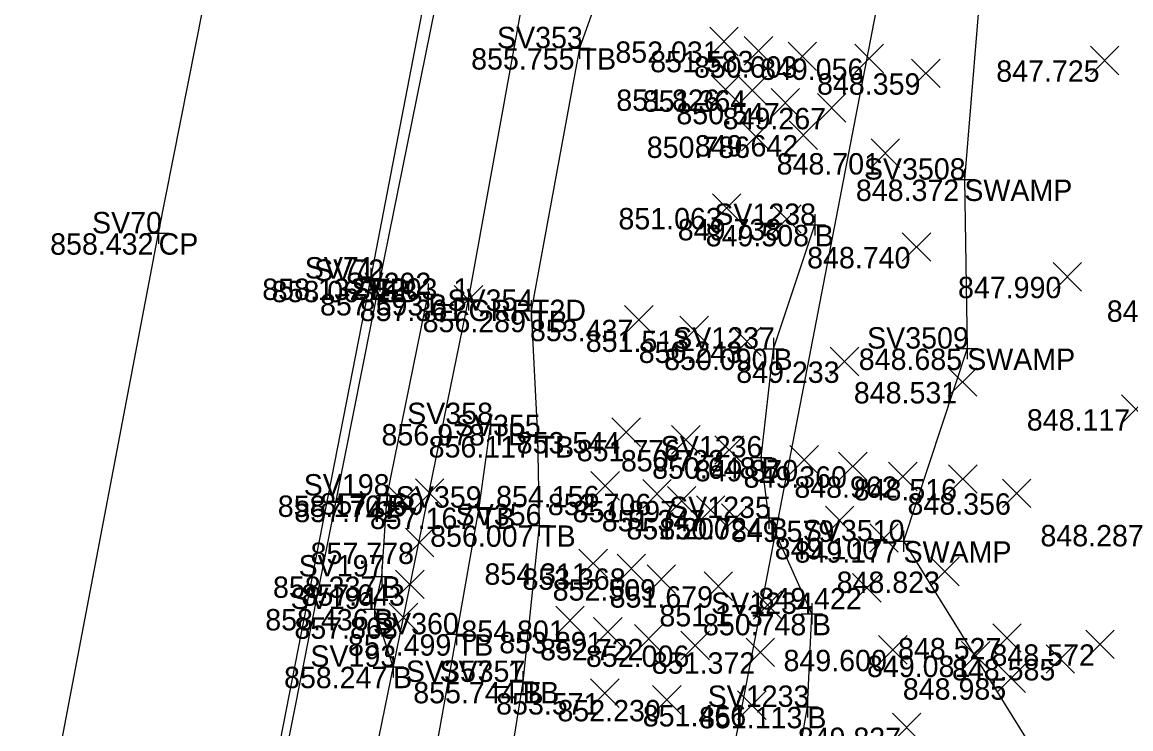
# Model space of a CAD drawing. Extents: x 2228183 to 2230895, y 679226 to 682223.
# Drawn here: x 2228291.3 to 2228343.2, y 680493.8 to 680526.8 of the extents above; entities that cross this region are included whole.
import ezdxf

# ---------------------------------------------------------------- set-up
doc = ezdxf.new("R2010")
doc.units = 0
for name, color, linetype in [('HY_X_Water_Edge', 7, 'Continuous'), ('PV_X_COP', 7, 'Continuous'), ('PV_X_EOP', 7, 'Continuous'), ('PV_X_Shoulder_Aggregate', 7, 'Continuous'), ('RD_X_GR_Rt', 7, 'Continuous'), ('SC_Scratch1', 7, 'Continuous'), ('SV_P_Control_Cells_Set', 7, 'Continuous'), ('SV_X_Break_Lines', 7, 'Continuous'), ('SV_X_Random_Point', 7, 'Continuous'), ('SV_X_Shot_Marker', 7, 'Continuous'), ('SV_X_Text_Comment', 7, 'Continuous'), ('SV_X_Top_of_Bank', 7, 'Continuous'), ('UT_X_Telecom', 7, 'Continuous')]:
    doc.layers.add(name, color=color, linetype=linetype)

msp = doc.modelspace()

# ---------------------------------------------------------------- linework, layer by layer
at = {"layer": 'HY_X_Water_Edge'}
msp.add_lwpolyline([(2228388.587, 680538.705), (2228381.654, 680540.428), (2228373.267, 680534.114), (2228362.534, 680538.041), (2228352.058, 680544.515), (2228344.28, 680554.272), (2228336.684, 680545.185), (2228336.291, 680530.248), (2228335.4, 680519.473), (2228335.533, 680511.573), (2228332.556, 680502.567), (2228338.972, 680492.245), (2228338.927, 680481.209), (2228345.953, 680472.044), (2228352.301, 680471.046)], dxfattribs=at)
at = {"layer": 'PV_X_COP'}
msp.add_lwpolyline([(2228262.604, 680193.524), (2228262.146, 680218.328), (2228262.437, 680243.717), (2228263.104, 680268.902), (2228264.443, 680294.535), (2228266.222, 680319.78), (2228268.589, 680344.685), (2228271.405, 680369.17), (2228274.939, 680394.252), (2228278.914, 680418.584), (2228283.486, 680443.605), (2228288.154, 680467.93), (2228293.014, 680492.349), (2228297.716, 680516.963), (2228302.55, 680541.357), (2228307.231, 680565.55), (2228311.972, 680589.697), (2228316.792, 680614.507), (2228321.818, 680639.234), (2228326.722, 680663.726), (2228331.754, 680688.345)], dxfattribs=at)
at = {"layer": 'PV_X_EOP'}
msp.add_lwpolyline([(2228272.958, 680193.788), (2228272.514, 680218.749), (2228272.761, 680243.66), (2228273.456, 680268.53), (2228274.726, 680293.686), (2228276.435, 680318.586), (2228278.817, 680343.424), (2228281.861, 680368.095), (2228285.158, 680392.512), (2228289.018, 680417.009), (2228293.5, 680441.465), (2228298.055, 680466.05), (2228302.846, 680490.329), (2228307.636, 680514.848), (2228312.366, 680539.332), (2228317.173, 680563.701), (2228322.066, 680588.07), (2228326.883, 680612.686), (2228331.837, 680637.002), (2228336.903, 680661.667), (2228341.796, 680685.984)], dxfattribs=at)
at = {"layer": 'PV_X_Shoulder_Aggregate'}
msp.add_lwpolyline([(2228273.386, 680193.772), (2228272.957, 680218.691), (2228273.264, 680243.644), (2228274.133, 680268.478), (2228275.472, 680293.621), (2228277.239, 680318.511), (2228279.649, 680343.317), (2228282.622, 680367.988), (2228285.854, 680392.371), (2228289.575, 680416.853), (2228293.89, 680441.38), (2228298.61, 680465.949), (2228303.2, 680490.238), (2228308.065, 680514.741), (2228313.026, 680539.169), (2228317.996, 680563.53), (2228322.869, 680587.896), (2228327.71, 680612.549), (2228332.443, 680636.855), (2228337.368, 680661.526), (2228342.398, 680685.817)], dxfattribs=at)
at = {"layer": 'RD_X_GR_Rt'}
msp.add_lwpolyline([(2228290.359, 680391.22), (2228294.274, 680415.932), (2228298.414, 680440.801), (2228302.718, 680465.177), (2228307.188, 680489.321), (2228312.206, 680513.859), (2228316.706, 680538.587), (2228321.519, 680562.878), (2228326.574, 680587.113), (2228331.32, 680611.864), (2228336.079, 680636.156), (2228341.093, 680660.882), (2228346.244, 680685.06), (2228350.849, 680709.572), (2228355.751, 680733.95), (2228357.804, 680743.718), (2228360.585, 680755.706), (2228364.08, 680768.892), (2228368.125, 680781.145)], dxfattribs=at)
at = {"layer": 'SV_X_Break_Lines'}
for points in [[(2228327.962, 680488.164), (2228327.281, 680490.374), (2228328.057, 680494.824), (2228328.274, 680499.17), (2228326.262, 680503.654), (2228325.899, 680506.488), (2228326.476, 680511.569), (2228328.404, 680517.354)], [(2228308.678, 680496.699), (2228307.807, 680499.399), (2228308.16, 680500.92), (2228308.403, 680504.705), (2228310.327, 680514.121)], [(2228314.747, 680495.992), (2228314.241, 680492.773), (2228314.211, 680488.538), (2228311.578, 680478.889), (2228311.017, 680474.372), (2228309.793, 680468.535), (2228309.215, 680465.931), (2228309.05, 680463.646), (2228307.936, 680454.458), (2228306.438, 680447.736), (2228305.961, 680443.231)]]:
    msp.add_lwpolyline(points, dxfattribs=at)
at = {"layer": 'SV_X_Random_Point'}
for p, q in [((2228323.491, 680525.265), (2228324.825, 680526.6)), ((2228323.491, 680526.6), (2228324.825, 680525.265)), ((2228325.104, 680524.824), (2228326.438, 680526.159)), ((2228325.104, 680526.159), (2228326.438, 680524.824)), ((2228327.153, 680524.57), (2228328.487, 680525.905)), ((2228327.153, 680525.905), (2228328.487, 680524.57)), ((2228330.283, 680524.467), (2228331.617, 680525.802)), ((2228330.283, 680525.802), (2228331.617, 680524.467)), ((2228341.295, 680524.377), (2228342.629, 680525.712)), ((2228341.295, 680525.712), (2228342.629, 680524.377)), ((2228332.929, 680523.775), (2228334.263, 680525.11)), ((2228332.929, 680525.11), (2228334.263, 680523.775)), ((2228323.558, 680523.019), (2228324.892, 680524.354)), ((2228323.558, 680524.354), (2228324.892, 680523.019)), ((2228324.815, 680522.978), (2228326.149, 680524.313)), ((2228324.815, 680524.313), (2228326.149, 680522.978)), ((2228326.361, 680522.392), (2228327.695, 680523.727)), ((2228326.361, 680523.727), (2228327.695, 680522.392)), ((2228328.528, 680522.159), (2228329.862, 680523.494)), ((2228328.528, 680523.494), (2228329.862, 680522.159)), ((2228327.202, 680520.885), (2228328.536, 680522.22)), ((2228327.202, 680522.22), (2228328.536, 680520.885)), ((2228324.984, 680520.819), (2228326.318, 680522.154)), ((2228324.984, 680522.154), (2228326.318, 680520.819)), ((2228331.037, 680520.043), (2228332.371, 680521.378)), ((2228331.037, 680521.378), (2228332.371, 680520.043)), ((2228323.619, 680517.48), (2228324.953, 680518.815)), ((2228323.619, 680518.815), (2228324.953, 680517.48)), ((2228326.431, 680516.966), (2228327.765, 680518.301)), ((2228326.431, 680518.301), (2228327.765, 680516.966)), ((2228332.495, 680515.657), (2228333.829, 680516.992)), ((2228332.495, 680516.992), (2228333.829, 680515.657)), ((2228339.55, 680514.262), (2228340.884, 680515.597)), ((2228339.55, 680515.597), (2228340.884, 680514.262)), ((2228311.539, 680513.192), (2228312.873, 680514.527)), ((2228311.539, 680514.527), (2228312.873, 680513.192)), ((2228319.511, 680512.253), (2228320.845, 680513.588)), ((2228319.511, 680513.588), (2228320.845, 680512.253)), ((2228322.093, 680511.751), (2228323.427, 680513.086)), ((2228322.093, 680513.086), (2228323.427, 680511.751)), ((2228324.568, 680511.235), (2228325.902, 680512.57)), ((2228324.568, 680512.57), (2228325.902, 680511.235)), ((2228329.128, 680510.303), (2228330.462, 680511.638)), ((2228329.128, 680511.638), (2228330.462, 680510.303)), ((2228334.646, 680509.342), (2228335.98, 680510.677)), ((2228334.646, 680510.677), (2228335.98, 680509.342)), ((2228342.751, 680508.073), (2228344.085, 680509.408)), ((2228342.751, 680509.408), (2228344.085, 680508.073)), ((2228318.919, 680507.002), (2228320.253, 680508.337)), ((2228318.919, 680508.337), (2228320.253, 680507.002)), ((2228321.71, 680506.639), (2228323.044, 680507.974)), ((2228321.71, 680507.974), (2228323.044, 680506.639)), ((2228323.735, 680506.163), (2228325.069, 680507.498)), ((2228323.735, 680507.498), (2228325.069, 680506.163)), ((2228327.238, 680505.702), (2228328.572, 680507.037)), ((2228327.238, 680507.037), (2228328.572, 680505.702)), ((2228329.521, 680505.403), (2228330.855, 680506.738)), ((2228329.521, 680506.738), (2228330.855, 680505.403)), ((2228331.854, 680504.93), (2228333.188, 680506.265)), ((2228331.854, 680506.265), (2228333.188, 680504.93)), ((2228334.662, 680504.808), (2228335.996, 680506.143)), ((2228334.662, 680506.143), (2228335.996, 680504.808)), ((2228317.936, 680504.49), (2228319.27, 680505.825)), ((2228317.936, 680505.825), (2228319.27, 680504.49)), ((2228308.467, 680503.793), (2228309.801, 680505.128)), ((2228308.467, 680505.128), (2228309.801, 680503.793)), ((2228309.728, 680504.146), (2228311.062, 680505.481)), ((2228309.728, 680505.481), (2228311.062, 680504.146)), ((2228320.357, 680504.118), (2228321.691, 680505.453)), ((2228320.357, 680505.453), (2228321.691, 680504.118)), ((2228321.512, 680503.788), (2228322.846, 680505.123)), ((2228321.512, 680505.123), (2228322.846, 680503.788)), ((2228337.179, 680504.141), (2228338.513, 680505.476)), ((2228337.179, 680505.476), (2228338.513, 680504.141)), ((2228322.87, 680503.362), (2228324.204, 680504.697)), ((2228322.87, 680504.697), (2228324.204, 680503.362)), ((2228324.043, 680502.983), (2228325.377, 680504.318)), ((2228324.043, 680504.318), (2228325.377, 680502.983)), ((2228328.9, 680502.869), (2228330.234, 680504.204)), ((2228328.9, 680504.204), (2228330.234, 680502.869)), ((2228309.258, 680501.837), (2228310.592, 680503.172)), ((2228309.258, 680503.172), (2228310.592, 680501.837)), ((2228330.978, 680502.053), (2228332.312, 680503.388)), ((2228330.978, 680503.388), (2228332.312, 680502.053)), ((2228317.37, 680500.866), (2228318.704, 680502.201)), ((2228317.37, 680502.201), (2228318.704, 680500.866)), ((2228319.158, 680500.629), (2228320.492, 680501.964)), ((2228319.158, 680501.964), (2228320.492, 680500.629)), ((2228320.562, 680500.124), (2228321.896, 680501.459)), ((2228320.562, 680501.459), (2228321.896, 680500.124)), ((2228333.823, 680500.483), (2228335.157, 680501.818)), ((2228333.823, 680501.818), (2228335.157, 680500.483)), ((2228308.794, 680499.886), (2228310.128, 680501.221)), ((2228308.794, 680501.221), (2228310.128, 680499.886)), ((2228323.228, 680499.796), (2228324.562, 680501.131)), ((2228323.228, 680501.131), (2228324.562, 680499.796)), ((2228330.176, 680499.719), (2228331.51, 680501.054)), ((2228330.176, 680501.054), (2228331.51, 680499.719)), ((2228325.536, 680498.918), (2228326.87, 680500.253)), ((2228325.536, 680500.253), (2228326.87, 680498.918)), ((2228308.5, 680498.339), (2228309.834, 680499.674)), ((2228308.5, 680499.674), (2228309.834, 680498.339)), ((2228316.291, 680498.196), (2228317.625, 680499.531)), ((2228316.291, 680499.531), (2228317.625, 680498.196)), ((2228318.061, 680497.662), (2228319.395, 680498.997)), ((2228318.061, 680498.997), (2228319.395, 680497.662)), ((2228319.968, 680497.335), (2228321.302, 680498.67)), ((2228319.968, 680498.67), (2228321.302, 680497.335)), ((2228322.139, 680497.026), (2228323.473, 680498.361)), ((2228322.139, 680498.361), (2228323.473, 680497.026)), ((2228336.728, 680497.378), (2228338.062, 680498.713)), ((2228336.728, 680498.713), (2228338.062, 680497.378)), ((2228341.076, 680497.079), (2228342.41, 680498.414)), ((2228341.076, 680498.414), (2228342.41, 680497.079)), ((2228325.191, 680496.706), (2228326.525, 680498.041)), ((2228325.191, 680498.041), (2228326.525, 680496.706)), ((2228331.39, 680496.824), (2228332.724, 680498.159)), ((2228331.39, 680498.159), (2228332.724, 680496.824)), ((2228335.262, 680496.551), (2228336.596, 680497.886)), ((2228335.262, 680497.886), (2228336.596, 680496.551)), ((2228339.225, 680496.397), (2228340.559, 680497.732)), ((2228339.225, 680497.732), (2228340.559, 680496.397)), ((2228336.926, 680495.494), (2228338.26, 680496.829)), ((2228336.926, 680496.829), (2228338.26, 680495.494)), ((2228317.917, 680494.799), (2228319.251, 680496.134)), ((2228317.917, 680496.134), (2228319.251, 680494.799)), ((2228320.816, 680494.481), (2228322.15, 680495.816)), ((2228320.816, 680495.816), (2228322.15, 680494.481)), ((2228324.798, 680494.241), (2228326.132, 680495.576)), ((2228324.798, 680495.576), (2228326.132, 680494.241)), ((2228332.038, 680493.19), (2228333.372, 680494.525)), ((2228332.038, 680494.525), (2228333.372, 680493.19))]:
    msp.add_line(p, q, dxfattribs=at)
at = {"layer": 'SV_X_Shot_Marker'}
for p, q in [((2228317.404, 680526.116), (2228317.404, 680525.116)), ((2228316.904, 680525.616), (2228317.904, 680525.616)), ((2228317.404, 680525.616), (2228317.404, 680525.616)), ((2228335.4, 680519.973), (2228335.4, 680518.973)), ((2228334.9, 680519.473), (2228335.9, 680519.473)), ((2228335.4, 680519.473), (2228335.4, 680519.473)), ((2228328.404, 680517.854), (2228328.404, 680516.854)), ((2228297.716, 680517.463), (2228297.716, 680516.463)), ((2228327.904, 680517.354), (2228328.904, 680517.354)), ((2228328.404, 680517.354), (2228328.404, 680517.354)), ((2228297.216, 680516.963), (2228298.216, 680516.963)), ((2228297.716, 680516.963), (2228297.716, 680516.963)), ((2228307.636, 680515.348), (2228307.636, 680514.348)), ((2228308.065, 680515.241), (2228308.065, 680514.241)), ((2228307.136, 680514.848), (2228308.136, 680514.848)), ((2228307.565, 680514.741), (2228308.565, 680514.741)), ((2228307.636, 680514.848), (2228307.636, 680514.848)), ((2228308.065, 680514.741), (2228308.065, 680514.741)), ((2228310.327, 680514.621), (2228310.327, 680513.621)), ((2228309.827, 680514.121), (2228310.827, 680514.121)), ((2228310.327, 680514.121), (2228310.327, 680514.121)), ((2228312.206, 680514.359), (2228312.206, 680513.359)), ((2228311.706, 680513.859), (2228312.706, 680513.859)), ((2228312.206, 680513.859), (2228312.206, 680513.859)), ((2228315.147, 680513.839), (2228315.147, 680512.839)), ((2228314.647, 680513.339), (2228315.647, 680513.339)), ((2228315.147, 680513.339), (2228315.147, 680513.339)), ((2228326.476, 680512.069), (2228326.476, 680511.069)), ((2228335.533, 680512.073), (2228335.533, 680511.073)), ((2228325.976, 680511.569), (2228326.976, 680511.569)), ((2228326.476, 680511.569), (2228326.476, 680511.569)), ((2228335.033, 680511.573), (2228336.033, 680511.573)), ((2228335.533, 680511.573), (2228335.533, 680511.573)), ((2228313.24, 680508.544), (2228313.24, 680507.544)), ((2228312.74, 680508.044), (2228313.74, 680508.044)), ((2228313.24, 680508.044), (2228313.24, 680508.044)), ((2228315.442, 680507.98), (2228315.442, 680506.98)), ((2228314.942, 680507.48), (2228315.942, 680507.48)), ((2228315.442, 680507.48), (2228315.442, 680507.48)), ((2228325.899, 680506.988), (2228325.899, 680505.988)), ((2228325.399, 680506.488), (2228326.399, 680506.488)), ((2228325.899, 680506.488), (2228325.899, 680506.488)), ((2228308.403, 680505.205), (2228308.403, 680504.205)), ((2228307.903, 680504.705), (2228308.903, 680504.705)), ((2228308.403, 680504.705), (2228308.403, 680504.705)), ((2228312.693, 680504.639), (2228312.693, 680503.639)), ((2228312.193, 680504.139), (2228313.193, 680504.139)), ((2228312.693, 680504.139), (2228312.693, 680504.139)), ((2228326.262, 680504.154), (2228326.262, 680503.154)), ((2228315.512, 680503.808), (2228315.512, 680502.808)), ((2228325.762, 680503.654), (2228326.762, 680503.654)), ((2228326.262, 680503.654), (2228326.262, 680503.654)), ((2228315.012, 680503.308), (2228316.012, 680503.308)), ((2228315.512, 680503.308), (2228315.512, 680503.308)), ((2228332.556, 680503.067), (2228332.556, 680502.067)), ((2228332.056, 680502.567), (2228333.056, 680502.567)), ((2228332.556, 680502.567), (2228332.556, 680502.567)), ((2228307.66, 680500.92), (2228308.66, 680500.92)), ((2228308.16, 680501.42), (2228308.16, 680500.42)), ((2228308.16, 680500.92), (2228308.16, 680500.92)), ((2228307.807, 680499.899), (2228307.807, 680498.899)), ((2228307.307, 680499.399), (2228308.307, 680499.399)), ((2228307.807, 680499.399), (2228307.807, 680499.399)), ((2228328.274, 680499.67), (2228328.274, 680498.67)), ((2228327.774, 680499.17), (2228328.774, 680499.17)), ((2228328.274, 680499.17), (2228328.274, 680499.17)), ((2228311.655, 680498.717), (2228311.655, 680497.717)), ((2228311.155, 680498.217), (2228312.155, 680498.217)), ((2228311.655, 680498.217), (2228311.655, 680498.217)), ((2228308.678, 680497.199), (2228308.678, 680496.199)), ((2228308.178, 680496.699), (2228309.178, 680496.699)), ((2228308.678, 680496.699), (2228308.678, 680496.699)), ((2228314.747, 680496.492), (2228314.747, 680495.492)), ((2228314.747, 680496.492), (2228314.747, 680495.492)), ((2228314.247, 680495.992), (2228315.247, 680495.992)), ((2228314.247, 680495.992), (2228315.247, 680495.992)), ((2228314.747, 680495.992), (2228314.747, 680495.992)), ((2228314.747, 680495.992), (2228314.747, 680495.992)), ((2228328.057, 680495.324), (2228328.057, 680494.324)), ((2228327.557, 680494.824), (2228328.557, 680494.824)), ((2228328.057, 680494.824), (2228328.057, 680494.824))]:
    msp.add_line(p, q, dxfattribs=at)
at = {"layer": 'SV_X_Top_of_Bank'}
for points in [[(2228319.616, 680531.838), (2228317.404, 680525.616), (2228315.147, 680513.339), (2228315.442, 680507.48), (2228315.512, 680503.308), (2228314.747, 680495.992)], [(2228313.24, 680508.044), (2228312.693, 680504.139), (2228311.655, 680498.217), (2228309.921, 680488.581), (2228308.107, 680479.863), (2228307.043, 680474.864), (2228305.815, 680469.295), (2228305.987, 680466.983), (2228305.966, 680464.279), (2228304.125, 680455.586), (2228302.925, 680448.672), (2228301.763, 680443.689), (2228300.838, 680439.938), (2228299.782, 680433.077), (2228298.614, 680423.72), (2228298.016, 680421.452), (2228298.283, 680417.737), (2228297.819, 680415.042)]]:
    msp.add_lwpolyline(points, dxfattribs=at)
at = {"layer": 'UT_X_Telecom'}
msp.add_lwpolyline([(2228306.801, 680400.49), (2228337.511, 680559.672), (2228349.317, 680620.055), (2228359.383, 680671.523), (2228365.58, 680702.692), (2228381.421, 680781.425)], dxfattribs=at)

# ---------------------------------------------------------------- texts
at = {"layer": 'SC_Scratch1'}
for s, p in [('852.031', (2228319.076, 680524.932)), ('855.755', (2228312.334, 680524.616)), ('851.583', (2228320.707, 680524.491)), ('850.603', (2228322.756, 680524.237)), ('849.056', (2228325.846, 680524.134)), ('847.725', (2228336.892, 680524.044)), ('848.359', (2228328.512, 680523.442)), ('851.826', (2228319.121, 680522.686)), ('851.364', (2228320.36, 680522.645)), ('850.547', (2228321.932, 680522.059)), ('849.267', (2228324.099, 680521.826)), ('850.786', (2228320.547, 680520.486)), ('849.642', (2228322.796, 680520.552)), ('848.701', (2228326.622, 680519.71)), ('848.372', (2228330.327, 680518.473)), ('851.063', (2228319.222, 680517.147)), ('849.738', (2228321.998, 680516.633)), ('849.508', (2228323.304, 680516.354)), ('858.432', (2228292.643, 680515.963)), ('848.740', (2228328.048, 680515.324)), ('847.990', (2228335.103, 680513.929)), ('858.132', (2228302.563, 680513.848)), ('858.063', (2228303.001, 680513.741)), ('857.593', (2228305.263, 680513.121)), ('857.361', (2228307.124, 680512.859)), ('857.361', (2228307.124, 680512.859)), ('847.940', (2228342.062, 680512.824)), ('856.289', (2228310.063, 680512.339)), ('853.437', (2228315.082, 680511.92)), ('851.513', (2228317.696, 680511.418)), ('850.243', (2228320.171, 680510.902)), ('850.090', (2228321.362, 680510.569)), ('848.685', (2228330.463, 680510.573)), ('849.233', (2228324.731, 680509.97)), ('848.531', (2228330.231, 680509.009)), ('848.117', (2228338.322, 680507.74)), ('856.978', (2228308.14, 680507.044)), ('853.544', (2228314.464, 680506.669)), ('856.117', (2228310.346, 680506.48)), ('851.776', (2228317.273, 680506.306)), ('850.723', (2228319.338, 680505.83)), ('850.648', (2228320.799, 680505.488)), ('849.870', (2228322.791, 680505.369)), ('849.360', (2228325.074, 680505.07)), ('848.962', (2228327.448, 680504.597)), ('854.156', (2228313.499, 680504.157)), ('848.516', (2228330.225, 680504.475)), ('858.170', (2228303.289, 680503.705)), ('857.560', (2228305.281, 680503.813)), ('852.706', (2228315.92, 680503.785)), ('848.356', (2228332.742, 680503.808)), ('857.742', (2228304.061, 680503.46)), ('857.167', (2228307.597, 680503.139)), ('851.897', (2228317.083, 680503.455)), ('851.347', (2228318.441, 680503.029)), ('851.200', (2228319.596, 680502.65)), ('850.724', (2228321.14, 680502.654)), ('849.579', (2228324.483, 680502.536)), ('856.007', (2228310.416, 680502.308)), ('848.287', (2228338.959, 680502.33)), ('857.778', (2228304.825, 680501.504)), ('849.100', (2228326.531, 680501.72)), ('849.177', (2228327.46, 680501.567)), ('854.311', (2228312.955, 680500.533)), ('858.337', (2228303.064, 680499.92)), ('853.368', (2228314.725, 680500.296)), ('848.823', (2228329.426, 680500.15)), ('857.643', (2228304.397, 680499.553)), ('852.509', (2228316.145, 680499.791)), ('851.679', (2228318.811, 680499.463)), ('849.422', (2228325.77, 680499.386)), ('858.436', (2228302.703, 680498.399)), ('851.173', (2228321.139, 680498.585)), ('857.868', (2228304.067, 680498.006)), ('854.801', (2228311.876, 680497.863)), ('850.748', (2228323.174, 680498.17)), ('853.891', (2228313.646, 680497.329)), ('857.499', (2228306.571, 680497.217)), ('852.722', (2228315.562, 680497.002)), ('848.527', (2228332.299, 680497.045)), ('852.006', (2228317.702, 680496.693)), ('851.372', (2228320.785, 680496.373)), ('849.600', (2228326.943, 680496.491)), ('848.572', (2228336.67, 680496.746)), ('849.081', (2228330.847, 680496.218)), ('848.585', (2228334.822, 680496.064)), ('858.247', (2228303.582, 680495.699)), ('855.744', (2228309.625, 680494.992)), ('855.744', (2228309.625, 680494.992)), ('848.985', (2228332.523, 680495.161)), ('853.571', (2228313.502, 680494.466)), ('852.230', (2228316.369, 680494.148)), ('851.466', (2228320.361, 680493.908)), ('851.113', (2228322.993, 680493.824)), ('849.837', (2228327.609, 680492.857))]:
    msp.add_text(s, height=1, dxfattribs=at).set_placement(p)
at = {"layer": 'SV_P_Control_Cells_Set'}
for s, p in [('SV353', (2228313.54, 680525.616)), ('SV3508', (2228330.701, 680519.473)), ('SV1238', (2228323.705, 680517.354)), ('SV70', (2228294.601, 680516.963)), ('SV71', (2228304.552, 680514.848)), ('SV72', (2228304.99, 680514.741)), ('SV202', (2228306.454, 680514.121)), ('SV203_1', (2228306.741, 680513.859)), ('SV354', (2228311.225, 680513.339)), ('SV1237', (2228321.782, 680511.569)), ('SV3509', (2228330.851, 680511.573)), ('SV358', (2228309.34, 680508.044)), ('SV355', (2228311.572, 680507.48)), ('SV1236', (2228321.197, 680506.488)), ('SV198', (2228304.503, 680504.705)), ('SV359', (2228308.809, 680504.139)), ('SV1235', (2228321.593, 680503.654)), ('SV356', (2228311.608, 680503.308)), ('SV3510', (2228327.844, 680502.567)), ('SV197', (2228304.264, 680500.92)), ('SV194', (2228303.885, 680499.399)), ('SV1234', (2228323.554, 680499.17)), ('SV360', (2228307.741, 680498.217)), ('SV193', (2228304.814, 680496.699)), ('SV357_1', (2228309.282, 680495.992)), ('SV357', (2228310.851, 680495.992)), ('SV1233', (2228323.395, 680494.824))]:
    msp.add_text(s, height=1, dxfattribs=at).set_placement(p)
at = {"layer": 'SV_X_Text_Comment'}
for s, p in [('TB', (2228317.404, 680524.616)), ('SWAMP', (2228335.4, 680518.473)), ('B', (2228328.404, 680516.354)), ('CP', (2228297.716, 680515.963)), ('EP', (2228307.636, 680513.848)), ('EB', (2228308.065, 680513.741)), ('B', (2228310.327, 680513.121)), ('GRRT2D', (2228312.206, 680512.859)), ('TB', (2228315.147, 680512.339)), ('B', (2228326.476, 680510.569)), ('SWAMP', (2228335.533, 680510.573)), ('TB', (2228313.24, 680507.044)), ('TB', (2228315.442, 680506.48)), ('B', (2228325.899, 680505.488)), ('B', (2228308.403, 680503.705)), ('TB', (2228312.693, 680503.139)), ('B', (2228326.262, 680502.654)), ('TB', (2228315.512, 680502.308)), ('SWAMP', (2228332.556, 680501.567)), ('B', (2228308.16, 680499.92)), ('B', (2228307.807, 680498.399)), ('B', (2228328.274, 680498.17)), ('TB', (2228311.655, 680497.217)), ('B', (2228308.678, 680495.699)), ('TB', (2228314.747, 680494.992)), ('B', (2228314.747, 680494.992)), ('B', (2228328.057, 680493.824))]:
    msp.add_text(s, height=1, dxfattribs=at).set_placement(p)

doc.saveas('drawing.dxf')
